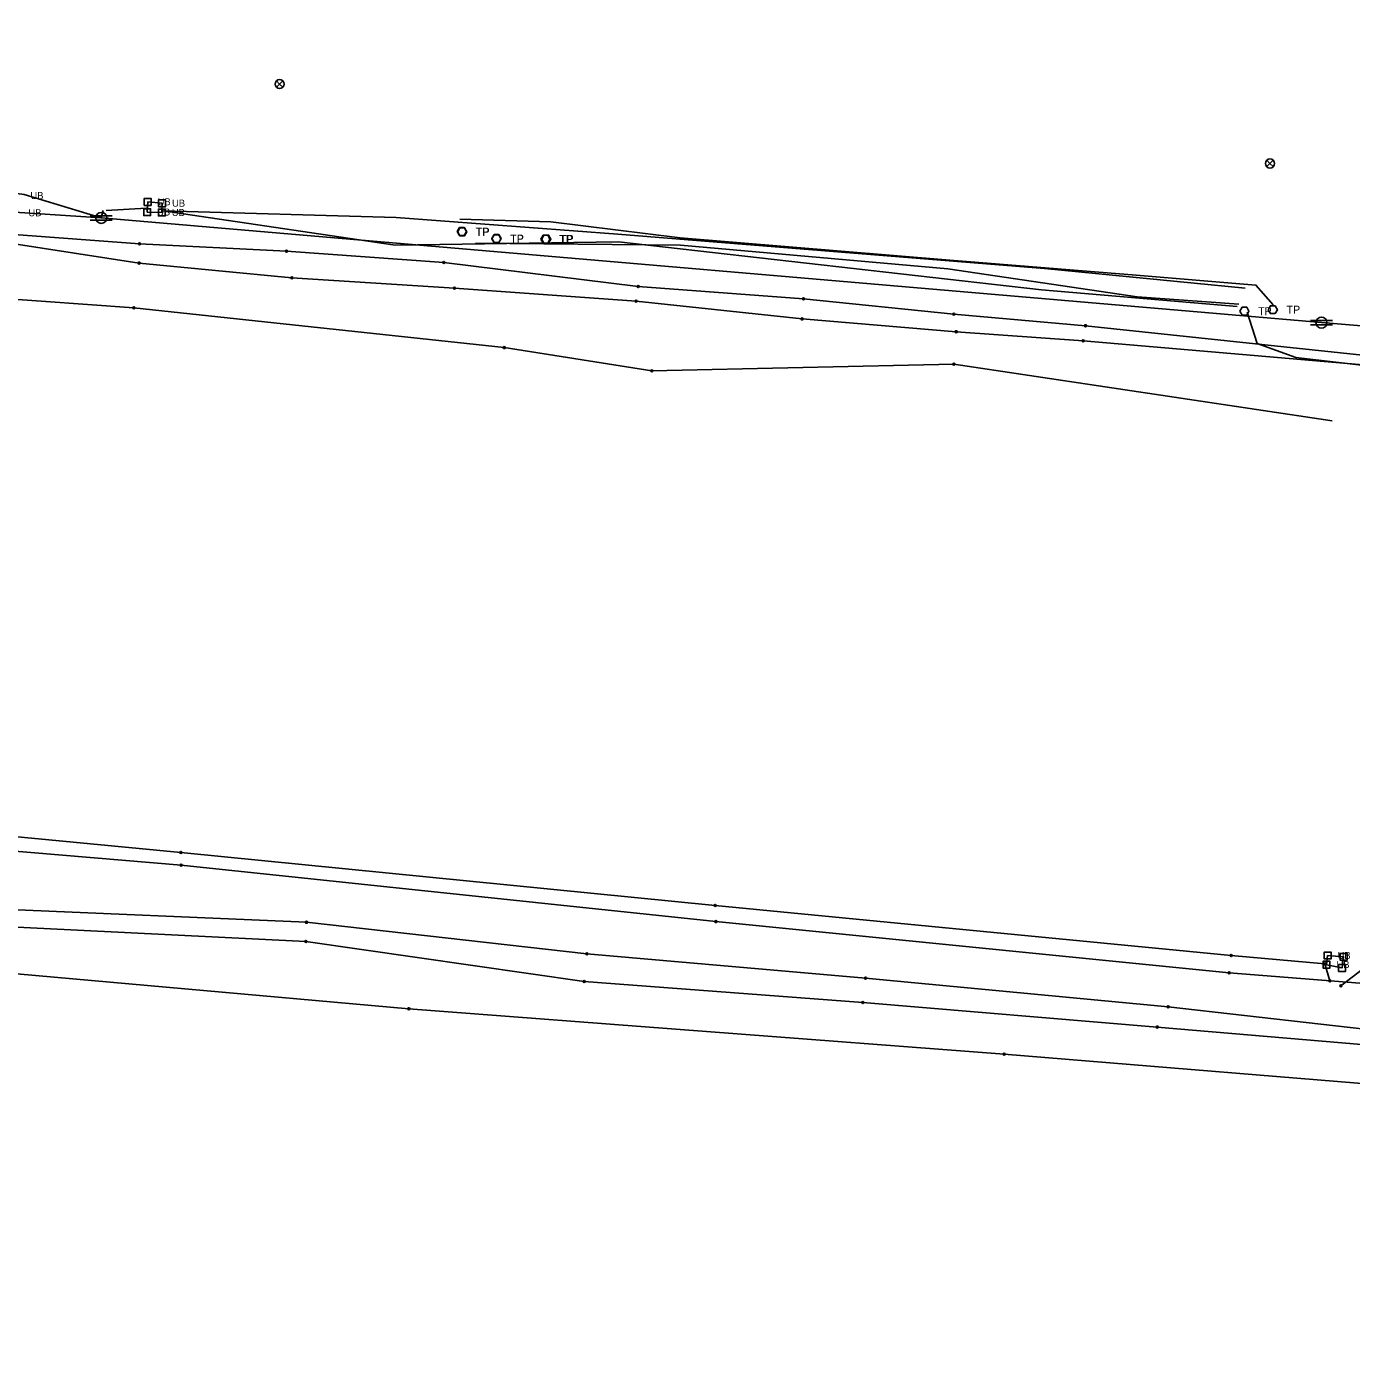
# Model space of a CAD drawing. Extents: x 20500343 to 20505311, y 7953484 to 7954193.
# Drawn here: x 20502927.2 to 20503191.9, y 7953635.3 to 7953900.5 of the extents above; entities that cross this region are included whole.
import ezdxf

# ---------------------------------------------------------------- set-up
doc = ezdxf.new("R2010")
doc.units = 0
for name, color, linetype in [('C-PROP-LINE-LOT', 7, 'Continuous'), ('V-ANNO-NOTE', 7, 'Continuous'), ('V-CTRL-HVPT', 7, 'Continuous'), ('V-MON-FND', 7, 'Continuous'), ('V-SITE-FENC', 7, 'Continuous'), ('V-SSWR-STRC', 7, 'Continuous')]:
    doc.layers.add(name, color=color, linetype=linetype)

msp = doc.modelspace()

# ---------------------------------------------------------------- linework, layer by layer
at = {"layer": 'C-PROP-LINE-LOT'}
for p, q in [((20503185.95, 7953841.37), (20503437.68, 7953820.69)), ((20503112.49, 7953833.07), (20503188.09, 7953821.73))]:
    msp.add_line(p, q, dxfattribs=at)
for points in [[(20502770.58, 7953900.5), (20502778.64, 7953888), (20502803.68, 7953879.58), (20502815.92, 7953875.93), (20502894.16, 7953871.34), (20502926.75, 7953866.94), (20502942.15, 7953862.29), (20502942.54, 7953863.75)], [(20502692.45, 7953878.59), (20502942.15, 7953862.29), (20503185.94, 7953841.4)], [(20502619.3, 7953874.37), (20502654.48, 7953870.28), (20502729.02, 7953862.23), (20502796.55, 7953856.97), (20502877.1, 7953849.29), (20502920.79, 7953846.35), (20502948.65, 7953844.32)], [(20502923.89, 7953863.48), (20502923.87, 7953857.22), (20502949.69, 7953853.27), (20502980.21, 7953850.33), (20503012.7, 7953848.26), (20503049, 7953845.63), (20503082.17, 7953842.1), (20503112.95, 7953839.56), (20503138.35, 7953837.73), (20503193.47, 7953832.98), (20503218.34, 7953830.79), (20503248.23, 7953827.27), (20503280.04, 7953825.39), (20503302.66, 7953821.04), (20503373.35, 7953815.08), (20503420.82, 7953809.31), (20503465.76, 7953808.12), (20503523.4, 7953802.43), (20503558.95, 7953800.72), (20503614.46, 7953794.57), (20503665.44, 7953787.94), (20503677.02, 7953787.65), (20503693.06, 7953785.61)], [(20502923.89, 7953863.47), (20502924.73, 7953858.96), (20502949.8, 7953857.13), (20502979.15, 7953855.66), (20503010.57, 7953853.39), (20503049.45, 7953848.56), (20503082.45, 7953846.12), (20503112.47, 7953843.06), (20503138.8, 7953840.76), (20503301.69, 7953823.49), (20503373.91, 7953818.29), (20503420.2, 7953815.98), (20503466.21, 7953810.37), (20503524.2, 7953805.14), (20503558.57, 7953802.46), (20503613.81, 7953798.05), (20503665.73, 7953789.96), (20503676.95, 7953790.93), (20503697.66, 7953791.85), (20503755.76, 7953785.45), (20503787.39, 7953784.49)], [(20502951.21, 7953864.26), (20502943.15, 7953863.74)], [(20502954.5, 7953863.68), (20503001.08, 7953862.38), (20503045.34, 7953859.06), (20503130.62, 7953852.16), (20503170.69, 7953848.24)], [(20502954.5, 7953863.68), (20503000.88, 7953856.87), (20503045.47, 7953857.52), (20503130.01, 7953847.91), (20503169.08, 7953844.62)], [(20503013.76, 7953862.05), (20503032, 7953861.47), (20503057.81, 7953858.32), (20503111.67, 7953853.84), (20503148.95, 7953850.85), (20503172.84, 7953848.87), (20503176.27, 7953844.94)], [(20503016.9, 7953857.23), (20503057.89, 7953856.86), (20503111.31, 7953852.1), (20503149.1, 7953846.5), (20503169.43, 7953845.07)], [(20502948.65, 7953844.32), (20503022.67, 7953836.37), (20503052.13, 7953831.74), (20503112.49, 7953833.07)], [(20503171.09, 7953843.45), (20503173.08, 7953837.17), (20503180.82, 7953834.4), (20503209.91, 7953830.98), (20503251.16, 7953828.52)], [(20502585.16, 7953780.62), (20502703.53, 7953770.96), (20502778.6, 7953753.43), (20502855.95, 7953745.33), (20502958.04, 7953735.55), (20503064.82, 7953724.97), (20503167.9, 7953714.97), (20503186.63, 7953713.33), (20503187.62, 7953709.92)], [(20502583.99, 7953772.95), (20502610.65, 7953768.87), (20502654.81, 7953765.56), (20502704, 7953762.66), (20502780.84, 7953747.28), (20502856.1, 7953741.6), (20502958.12, 7953733.02), (20503064.96, 7953721.73), (20503167.51, 7953711.49), (20503200.31, 7953708.91), (20503261.33, 7953704.35), (20503308.48, 7953700.62), (20503425.37, 7953689.03), (20503525.59, 7953683.92), (20503632.36, 7953675.44)], [(20502567.82, 7953767.29), (20502613.16, 7953765.86), (20502660.75, 7953761.57), (20502684.96, 7953758.32), (20502704.25, 7953752.73), (20502749.31, 7953741.65), (20502800.87, 7953733.72), (20502861.3, 7953730.84), (20502920.69, 7953724.3), (20502983.15, 7953721.6), (20503039.18, 7953715.3), (20503094.87, 7953710.44), (20503155.33, 7953704.72), (20503201.09, 7953699.55), (20503255.71, 7953694.61), (20503304.33, 7953690.28), (20503344.16, 7953687.19), (20503374.46, 7953685.7), (20503426.83, 7953682.97), (20503524.49, 7953672.95), (20503631.72, 7953664.81)], [(20502567.9, 7953761.34), (20502613.51, 7953762.6), (20502660.72, 7953759.56), (20502684.44, 7953756.31), (20502703.23, 7953750.18), (20502747.73, 7953738.37), (20502800.44, 7953730.37), (20502860.52, 7953724.51), (20502919.86, 7953720.87), (20502983.04, 7953717.79), (20503038.66, 7953709.78), (20503094.29, 7953705.56), (20503153.13, 7953700.69), (20503201.01, 7953696.62), (20503255.42, 7953690.81), (20503303.52, 7953686.48), (20503344.16, 7953683.02), (20503374.14, 7953680.96), (20503426.87, 7953677.14), (20503523.93, 7953669.23), (20503630.84, 7953663.08)], [(20502753.52, 7953725.91), (20502816.21, 7953720.99), (20502880.43, 7953715.32), (20503003.58, 7953704.35), (20503122.54, 7953695.27), (20503239.48, 7953685.69), (20503360, 7953675.01), (20503474.19, 7953666.22), (20503697.41, 7953647.35), (20503810.09, 7953637.77), (20503838.81, 7953635.29)], [(20503189.83, 7953708.93), (20503196.34, 7953713.92), (20503254.07, 7953707.55), (20503309.11, 7953704.37), (20503425.93, 7953696.5), (20503526.62, 7953689.02), (20503632.63, 7953678.56)]]:
    msp.add_lwpolyline(points, dxfattribs=at)
at = {"layer": 'V-ANNO-NOTE'}
for centre in [(20502949.8, 7953857.13), (20502979.15, 7953855.66), (20502949.69, 7953853.27), (20503010.57, 7953853.39), (20502980.21, 7953850.33), (20503012.7, 7953848.26), (20503049.45, 7953848.56), (20503082.45, 7953846.12), (20502948.65, 7953844.32), (20503049, 7953845.63), (20503082.17, 7953842.1), (20503112.47, 7953843.06), (20503138.8, 7953840.76), (20503112.95, 7953839.56), (20503022.67, 7953836.37), (20503138.35, 7953837.73), (20503112.49, 7953833.07), (20503052.13, 7953831.74), (20502958.04, 7953735.55), (20502958.12, 7953733.02), (20503064.82, 7953724.97), (20502983.15, 7953721.6), (20503064.96, 7953721.73), (20502983.04, 7953717.79), (20503039.18, 7953715.3), (20503167.9, 7953714.97), (20503167.51, 7953711.49), (20503186.63, 7953713.33), (20503038.66, 7953709.78), (20503094.87, 7953710.44), (20503187.62, 7953709.92), (20503189.83, 7953708.93), (20503094.29, 7953705.56), (20503003.58, 7953704.35), (20503155.33, 7953704.72), (20503153.13, 7953700.69), (20503122.54, 7953695.27)]:
    msp.add_circle(centre, 0.2, dxfattribs=at)
at = {"layer": 'V-CTRL-HVPT'}
for p, q in [((20502939.95, 7953862.73), (20502944.35, 7953862.73)), ((20502939.95, 7953861.85), (20502944.35, 7953861.85)), ((20503183.75, 7953841.81), (20503188.15, 7953841.81)), ((20503183.75, 7953840.93), (20503188.15, 7953840.93))]:
    msp.add_line(p, q, dxfattribs=at)
for centre in [(20502942.15, 7953862.29), (20503185.95, 7953841.37)]:
    msp.add_circle(centre, 1.1, dxfattribs=at)
at = {"layer": 'V-MON-FND'}
for points in [[(20502951.32, 7953863.44), (20502954.25, 7953863.35), (20502954.3, 7953865.21), (20502951.42, 7953865.48)], [(20502951.32, 7953863.44), (20502954.25, 7953863.35), (20502954.3, 7953865.21), (20502951.42, 7953865.48)], [(20503187.18, 7953714.97), (20503190.38, 7953714.71), (20503190.06, 7953712.48), (20503186.95, 7953713.13)], [(20503187.18, 7953714.97), (20503190.38, 7953714.71), (20503190.06, 7953712.48), (20503186.95, 7953713.13)]]:
    msp.add_lwpolyline(points, close=True, dxfattribs=at)
for points in [[(20503013.36, 7953859.5), (20503013.81, 7953860.29), (20503014.73, 7953860.29), (20503015.18, 7953859.5), (20503014.73, 7953858.71), (20503013.81, 7953858.71), (20503013.36, 7953859.5)], [(20503020.18, 7953858.09), (20503020.63, 7953858.89), (20503021.55, 7953858.89), (20503022, 7953858.09), (20503021.55, 7953857.3), (20503020.63, 7953857.3), (20503020.18, 7953858.09)], [(20503029.98, 7953858.04), (20503030.43, 7953858.83), (20503031.35, 7953858.83), (20503031.8, 7953858.04), (20503031.35, 7953857.25), (20503030.43, 7953857.25), (20503029.98, 7953858.04)], [(20503030.15, 7953858.06), (20503030.6, 7953858.86), (20503031.52, 7953858.86), (20503031.97, 7953858.06), (20503031.52, 7953857.27), (20503030.6, 7953857.27), (20503030.15, 7953858.06)], [(20503169.63, 7953843.64), (20503170.08, 7953844.43), (20503171, 7953844.43), (20503171.45, 7953843.64), (20503171, 7953842.85), (20503170.08, 7953842.85), (20503169.63, 7953843.64)], [(20503175.31, 7953843.95), (20503175.76, 7953844.75), (20503176.68, 7953844.75), (20503177.13, 7953843.95), (20503176.68, 7953843.16), (20503175.76, 7953843.16), (20503175.31, 7953843.95)]]:
    msp.add_lwpolyline(points, dxfattribs=at)
at = {"layer": 'V-SITE-FENC'}
for points in [[(20502951.42, 7953864.79), (20502951.42, 7953864.79), (20502952.11, 7953864.79), (20502952.11, 7953866.17), (20502950.73, 7953866.17), (20502950.73, 7953864.79), (20502951.42, 7953864.79)], [(20502954.3, 7953864.52), (20502954.3, 7953864.52), (20502954.99, 7953864.52), (20502954.99, 7953865.9), (20502953.61, 7953865.9), (20502953.61, 7953864.52), (20502954.3, 7953864.52)], [(20502951.32, 7953862.75), (20502951.32, 7953862.75), (20502952.01, 7953862.75), (20502952.01, 7953864.12), (20502950.63, 7953864.12), (20502950.63, 7953862.75), (20502951.32, 7953862.75)], [(20502954.25, 7953862.67), (20502954.25, 7953862.67), (20502954.94, 7953862.67), (20502954.94, 7953864.04), (20502953.56, 7953864.04), (20502953.56, 7953862.67), (20502954.25, 7953862.67)], [(20503013.27, 7953859.55), (20503013.72, 7953860.34), (20503014.64, 7953860.34), (20503015.09, 7953859.55), (20503014.64, 7953858.76), (20503013.72, 7953858.76), (20503013.27, 7953859.55)], [(20503020.2, 7953858.15), (20503020.65, 7953858.94), (20503021.57, 7953858.94), (20503022.02, 7953858.15), (20503021.57, 7953857.36), (20503020.65, 7953857.36), (20503020.2, 7953858.15)], [(20503186.95, 7953712.45), (20503186.95, 7953712.45), (20503187.64, 7953712.45), (20503187.64, 7953713.82), (20503186.26, 7953713.82), (20503186.26, 7953712.45), (20503186.95, 7953712.45)], [(20503187.18, 7953714.28), (20503187.18, 7953714.28), (20503187.87, 7953714.28), (20503187.87, 7953715.65), (20503186.49, 7953715.65), (20503186.49, 7953714.28), (20503187.18, 7953714.28)], [(20503190.38, 7953714.02), (20503190.38, 7953714.02), (20503191.07, 7953714.02), (20503191.07, 7953715.39), (20503189.69, 7953715.39), (20503189.69, 7953714.02), (20503190.38, 7953714.02)], [(20503190.06, 7953711.79), (20503190.06, 7953711.79), (20503190.75, 7953711.79), (20503190.75, 7953713.16), (20503189.37, 7953713.16), (20503189.37, 7953711.79), (20503190.06, 7953711.79)]]:
    msp.add_lwpolyline(points, dxfattribs=at)
at = {"layer": 'V-SSWR-STRC'}
for points in [[(20502977.14, 7953888.37), (20502977.78, 7953889), (20502977.14, 7953889.64)], [(20502978.42, 7953889.64), (20502977.78, 7953889), (20502978.42, 7953888.37)], [(20503175.02, 7953872.52), (20503175.66, 7953873.15), (20503175.02, 7953873.79)], [(20503176.3, 7953873.79), (20503175.66, 7953873.15), (20503176.3, 7953872.52)]]:
    msp.add_lwpolyline(points, dxfattribs=at)
for centre, start, end in [((20502977.78, 7953889), 135, 225), ((20502977.78, 7953889), 45, 135), ((20502977.78, 7953889), 315, 45), ((20502977.78, 7953889), 225, 315), ((20503175.66, 7953873.15), 135, 225), ((20503175.66, 7953873.15), 45, 135), ((20503175.66, 7953873.15), 315, 45), ((20503175.66, 7953873.15), 225, 315)]:
    msp.add_arc(centre, 0.899, start, end, dxfattribs=at)

# ---------------------------------------------------------------- texts
at = {"layer": 'V-MON-FND'}
for p in [(20503017.01, 7953858.7), (20503023.83, 7953857.29), (20503033.63, 7953857.24), (20503033.8, 7953857.27), (20503173.28, 7953842.84), (20503178.96, 7953843.16)]:
    msp.add_text('TP', height=1.599, dxfattribs=at).set_placement(p)
at = {"layer": 'V-SITE-FENC'}
for s, height, p in [('UB', 1.399, (20502927.99, 7953866.05)), ('UB', 1.399, (20502953.41, 7953864.8)), ('UB', 1.399, (20502956.29, 7953864.53)), ('UB', 1.399, (20502927.59, 7953862.61)), ('UB', 1.399, (20502953.31, 7953862.75)), ('UB', 1.399, (20502956.24, 7953862.67)), ('TP', 1.599, (20503016.92, 7953858.75)), ('TP', 1.599, (20503023.85, 7953857.35)), ('UB', 1.399, (20503188.94, 7953712.45)), ('UB', 1.399, (20503189.17, 7953714.29))]:
    msp.add_text(s, height=height, dxfattribs=at).set_placement(p)

doc.saveas('drawing.dxf')
